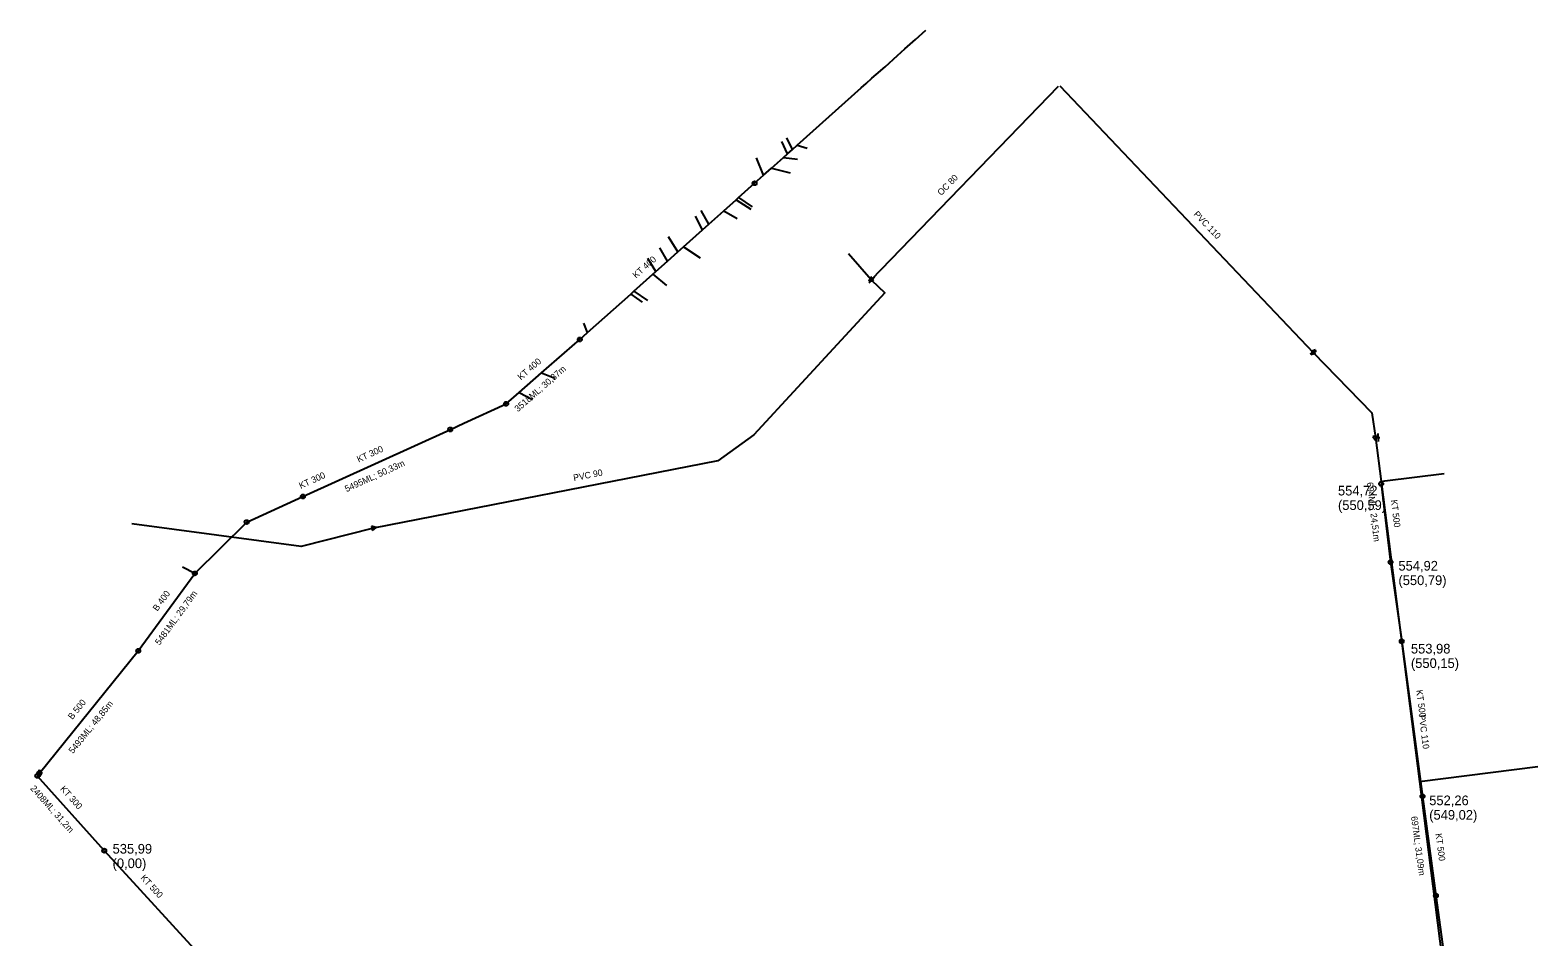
# Model space of a CAD drawing. Extents: x -867696 to -865033, y -1042522 to -1039817.
# Drawn here: x -867375 to -866906.6, y -1040222.5 to -1039941 of the extents above; entities that cross this region are included whole.
import ezdxf

# ---------------------------------------------------------------- set-up
doc = ezdxf.new("R2010")
doc.units = 0
for name, color, linetype in [('KN - jednotna', 7, 'Continuous'), ('KN - ostatni', 7, 'Continuous'), ('KN - popis material', 7, 'Continuous'), ('KN - popis ostatni', 7, 'Continuous'), ('KN - popis usek delka', 7, 'Continuous'), ('KN - pripojka', 7, 'Continuous'), ('KN - sachta komora', 7, 'Continuous'), ('Level 1', 7, 'Continuous'), ('V - armatura', 7, 'Continuous'), ('V - hydrant', 7, 'Continuous'), ('V - ostatni', 7, 'Continuous'), ('V - popis material', 7, 'Continuous'), ('V - pripojka', 7, 'Continuous'), ('V - rozvadeci', 7, 'Continuous')]:
    doc.layers.add(name, color=color, linetype=linetype)

# ---------------------------------------------------------------- blocks, each defined once
blk = doc.blocks.new('100.M')
at = {"layer": 'Level 1'}
blk.add_circle((0, 0), 1.27, dxfattribs=at)
blk = doc.blocks.new('104')
at = {"layer": 'Level 1'}
for p, q in [((-0.03, 1.05), (-0.64, -0.29)), ((0.32, 1.05), (-0.15, 0.09)), ((-0.15, 0.09), (0.74, 0.3)), ((0.74, 0.3), (0.06, -1.07)), ((-0.64, -0.29), (0.25, -0.08)), ((0.25, -0.08), (-0.24, -1.07))]:
    blk.add_line(p, q, dxfattribs=at)
blk = doc.blocks.new('111')
at = {"layer": 'Level 1'}
for p, q in [((0.42, 0.72), (-0.83, 0)), ((-0.83, 0), (0.42, -0.72)), ((0.42, -0.72), (0.42, 0.72))]:
    blk.add_line(p, q, dxfattribs=at)
blk = doc.blocks.new('147')
at = {"layer": 'Level 1'}
blk.add_line((0, 1.27), (0, -1.27), dxfattribs=at)
blk = doc.blocks.new('156')
at = {"layer": 'Level 1'}
for p, q in [((-0.07, 1.04), (-0.68, -0.3)), ((0.28, 1.04), (-0.19, 0.08)), ((-0.19, 0.08), (0.7, 0.29)), ((0.7, 0.29), (0.02, -1.08)), ((-0.68, -0.3), (0.21, -0.09)), ((0.21, -0.09), (-0.28, -1.08))]:
    blk.add_line(p, q, dxfattribs=at)
blk = doc.blocks.new('150')
at = {"layer": 'Level 1'}
blk.add_line((0, 1.27), (0, -1.27), dxfattribs=at)

msp = doc.modelspace()

# ---------------------------------------------------------------- linework, layer by layer
at = {"layer": 'KN - jednotna'}
for points in [[(-867149.906, -1039988.495), (-867147.098, -1039985.986), (-867144.635, -1039983.784), (-867140.899, -1039980.446), (-867139.667, -1039979.345), (-867138.135, -1039977.976), (-867136.649, -1039976.648), (-867116.78, -1039958.894), (-867115.289, -1039957.561), (-867113.438, -1039955.907), (-867112.154, -1039954.76), (-867109.39, -1039952.29), (-867105.55, -1039948.859), (-867103.239, -1039946.793), (-867099.908, -1039943.816), (-867096.7, -1039940.95)], [(-867204.209, -1040037.02), (-867201.764, -1040034.835), (-867188.395, -1040022.889), (-867187.448, -1040022.042), (-867181.527, -1040016.751), (-867180.584, -1040015.909), (-867176.998, -1040012.705), (-867173.784, -1040009.832), (-867171.957, -1040008.199), (-867166.058, -1040002.928), (-867164.116, -1040001.193), (-867159.443, -1039997.017), (-867155.638, -1039993.617), (-867154.904, -1039992.961), (-867149.906, -1039988.495)], [(-867227.096, -1040056.989), (-867223.008, -1040053.422), (-867216.124, -1040047.416), (-867204.209, -1040037.02)], [(-867244.415, -1040064.939), (-867240.283, -1040063.042), (-867227.096, -1040056.989)], [(-867290.231, -1040085.779), (-867244.415, -1040064.939)], [(-866955.268, -1040081.838), (-866952.339, -1040106.168)], [(-867307.687, -1040093.719), (-867290.231, -1040085.779)], [(-867323.792, -1040109.661), (-867307.687, -1040093.719)], [(-866952.339, -1040106.168), (-866948.859, -1040130.749)], [(-867341.382, -1040133.701), (-867323.792, -1040109.661)], [(-866948.859, -1040130.749), (-866942.407, -1040178.897)], [(-867372.097, -1040171.691), (-867341.382, -1040133.701)], [(-867372.759, -1040172.509), (-867372.097, -1040171.691)], [(-867351.948, -1040195.749), (-867372.759, -1040172.509)], [(-866942.407, -1040178.897), (-866938.241, -1040209.707)], [(-867351.948, -1040195.749), (-867319.518, -1040231.057)], [(-866938.241, -1040209.707), (-866935.579, -1040229.396)]]:
    msp.add_lwpolyline(points, dxfattribs=at)
at = {"layer": 'KN - pripojka'}
for points in [[(-867139.667, -1039979.345), (-867141.46, -1039975.495)], [(-867138.135, -1039977.976), (-867139.873, -1039974.375)], [(-867136.649, -1039976.648), (-867133.523, -1039977.55)], [(-867147.098, -1039985.986), (-867149.304, -1039980.631)], [(-867140.899, -1039980.446), (-867136.605, -1039981.005)], [(-867144.635, -1039983.784), (-867138.846, -1039985.3)], [(-867155.638, -1039993.617), (-867151.078, -1039996.506)], [(-867154.904, -1039992.961), (-867150.611, -1039995.852)], [(-867166.058, -1040002.928), (-867168.26, -1039998.747)], [(-867164.116, -1040001.193), (-867166.486, -1039996.973)], [(-867159.443, -1039997.017), (-867155.28, -1039999.401)], [(-867173.784, -1040009.832), (-867176.664, -1040005.097)], [(-867176.998, -1040012.705), (-867179.372, -1040008.552)], [(-867171.957, -1040008.199), (-867166.766, -1040011.633)], [(-867180.584, -1040015.909), (-867183.108, -1040011.82)], [(-867181.527, -1040016.751), (-867177.225, -1040020.224)], [(-867188.395, -1040022.889), (-867184.788, -1040025.453)], [(-867187.448, -1040022.042), (-867183.201, -1040024.893)], [(-867201.764, -1040034.835), (-867202.997, -1040031.897)], [(-867216.124, -1040047.416), (-867211.962, -1040048.985)], [(-867223.008, -1040053.422), (-867218.872, -1040055.615)], [(-867323.792, -1040109.661), (-867327.659, -1040107.721)]]:
    msp.add_lwpolyline(points, dxfattribs=at)
at = {"layer": 'V - pripojka'}
for points in [[(-867113.735, -1040018.433), (-867120.776, -1040010.453)], [(-866957.054, -1040067.457), (-866955.71, -1040067.43)], [(-866955.248, -1040081.074), (-866954.153, -1040080.921), (-866935.734, -1040078.611)], [(-867268.315, -1040095.579), (-867290.803, -1040101.269), (-867343.364, -1040094.225)], [(-866943.379, -1040174.303), (-866906.581, -1040169.669)]]:
    msp.add_lwpolyline(points, dxfattribs=at)
at = {"layer": 'V - rozvadeci'}
for points in [[(-867055.59, -1039958.47), (-867113.735, -1040018.433)], [(-867055.056, -1039958.189), (-866976.33, -1040041.043), (-866958.126, -1040059.839), (-866957.054, -1040067.457)], [(-867113.544, -1040018.616), (-867109.422, -1040022.496), (-867150.189, -1040066.59), (-867161.297, -1040074.718), (-867268.315, -1040095.579)], [(-867113.735, -1040018.433), (-867113.544, -1040018.616)], [(-866957.054, -1040067.457), (-866955.248, -1040081.074), (-866943.379, -1040174.303), (-866925.276, -1040316.515)]]:
    msp.add_lwpolyline(points, dxfattribs=at)

# ---------------------------------------------------------------- block references
at = {"layer": 'KN - ostatni'}
msp.add_blockref('104', (-867372.1, -1040171.69), dxfattribs=at)
at = {"layer": 'KN - sachta komora'}
for p, xscale, yscale, rotation in [((-867149.906, -1039988.495), 0.5000000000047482, 0.5000000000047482, 42.000001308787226), ((-867204.209, -1040037.02), 0.5000000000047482, 0.5000000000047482, 42.000001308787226), ((-867227.096, -1040056.989), 0.4999999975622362, 0.4999999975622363, 33.000001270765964), ((-867244.415, -1040064.939), 0.5084781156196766, 0.5084781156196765, 26.97601645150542), ((-867290.231, -1040085.779), 0.5084781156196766, 0.5084781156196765, 26.97601645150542), ((-866955.268, -1040081.838), 0.500095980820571, 0.500095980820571, -82.91099886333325), ((-867307.687, -1040093.719), 0.5000000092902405, 0.5000000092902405, 35.000000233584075), ((-867323.792, -1040109.661), 0.5000000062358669, 0.5000000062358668, 49.99999868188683), ((-866952.339, -1040106.168), 0.49999999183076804, 0.49999999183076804, 98.00000038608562), ((-866948.859, -1040130.749), 0.49999999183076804, 0.49999999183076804, 98.00000038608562), ((-867341.382, -1040133.701), 0.49999999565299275, 0.4999999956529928, 52.999998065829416), ((-867372.759, -1040172.509), 0.500000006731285, 0.5000000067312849, -88.00000009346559), ((-867372.097, -1040171.691), 0.5000000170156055, 0.5000000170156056, 51.999999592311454), ((-866942.407, -1040178.897), 0.49999999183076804, 0.49999999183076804, 98.00000038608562), ((-867351.948, -1040195.749), 0.50000000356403, 0.50000000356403, 133.00000056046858), ((-866938.241, -1040209.707), 0.49999999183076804, 0.49999999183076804, -81.99999961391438)]:
    msp.add_blockref('100.M', p, dxfattribs=dict(at, xscale=xscale, yscale=yscale, rotation=rotation))
at = {"layer": 'V - armatura', "xscale": 1.00000000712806, "yscale": 1.00000000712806, "rotation": -43.0000005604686}
msp.add_blockref('147', (-867113.544, -1040018.616), dxfattribs=at)
at = {"layer": 'V - hydrant', "xscale": 1.00000001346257, "yscale": 1.0000000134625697, "rotation": 1.9999999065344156}
msp.add_blockref('150', (-866956.248, -1040067.441), dxfattribs=at)
at = {"layer": 'V - ostatni'}
for name, p, xscale, yscale, rotation in [('111', (-867113.735, -1040018.433), 1.00000001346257, 1.0000000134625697, -88.00000009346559), ('156', (-866976.33, -1040041.043), 1.0000000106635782, 1.0000000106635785, -45.99999834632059), ('111', (-866957.054, -1040067.457), 1.0000000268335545, 1.0000000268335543, 93.99999971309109), ('111', (-867268.315, -1040095.579), 1.0045862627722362, 1.0045862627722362, -166.82590928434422)]:
    msp.add_blockref(name, p, dxfattribs=dict(at, xscale=xscale, yscale=yscale, rotation=rotation))

# ---------------------------------------------------------------- texts
at = {"layer": 'KN - popis material'}
for s, rotation, p in [('KT 400', 41.78, (-867186.701, -1040018.149)), ('KT 400', 41.1, (-867222.474, -1040049.77)), ('KT 300', 24.46, (-867272.904, -1040075.261)), ('KT 300', 24.46, (-867290.898, -1040083.442)), ('KT 500', 276.86, (-866952.242, -1040086.891)), ('B 400', 53.81, (-867335.462, -1040121.546)), ('KT 500', 277.63, (-866944.401, -1040145.952)), ('B 500', 51.04, (-867361.853, -1040155.203)), ('KT 300', 311.84, (-867365.78, -1040176.704)), ('KT 500', 277.7, (-866938.414, -1040190.518)), ('KT 500', 312.57, (-867340.809, -1040204.329))]:
    msp.add_text(s, height=2, rotation=rotation, dxfattribs=at).set_placement(p)
at = {"layer": 'KN - popis ostatni'}
for s, p in [('554,72 ', (-866968.668, -1040085.448)), ('(550,59)', (-866968.668, -1040089.948)), ('554,92 ', (-866949.889, -1040108.778)), ('(550,79)', (-866949.889, -1040113.278)), ('553,98 ', (-866946.009, -1040134.529)), ('(550,15)', (-866946.009, -1040139.029)), ('552,26 ', (-866940.327, -1040181.637)), ('(549,02)', (-866940.327, -1040186.137)), ('535,99 ', (-867349.348, -1040196.669)), ('(0,00)', (-867349.348, -1040201.169))]:
    msp.add_text(s, height=3, dxfattribs=at).set_placement(p)
at = {"layer": 'KN - popis usek delka'}
for s, rotation, p in [('3518ML; 30,37m', 41.1, (-867223.429, -1040059.627)), ('5495ML; 50,33m', 24.46, (-867276.642, -1040084.432)), ('694ML; 24,51m', 276.86, (-866959.745, -1040081.449)), ('5481ML; 29,79m', 53.81, (-867334.756, -1040132.098)), ('5493ML; 48,85m', 51.04, (-867361.658, -1040165.776)), ('2408ML; 31,2m', 311.84, (-867375.049, -1040176.547)), ('697ML; 31,09m', 277.7, (-866945.997, -1040185.186))]:
    msp.add_text(s, height=1.99999, rotation=rotation, dxfattribs=at).set_placement(p)
at = {"layer": 'V - popis material'}
for s, rotation, p in [('OC 80', 45.88, (-867091.905, -1039992.473)), ('PVC 110', 313.54, (-867013.675, -1039998.257)), ('PVC 90', 11.03, (-867206.023, -1040080.992)), ('PVC 110', 277.25, (-866943.587, -1040153.659))]:
    msp.add_text(s, height=2, rotation=rotation, dxfattribs=at).set_placement(p)

doc.saveas('drawing.dxf')
